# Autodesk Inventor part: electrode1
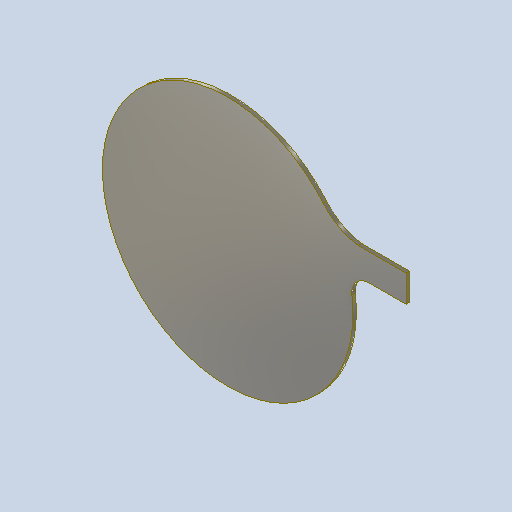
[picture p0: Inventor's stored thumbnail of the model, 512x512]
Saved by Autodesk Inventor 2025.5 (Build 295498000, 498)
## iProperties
Created: 2018-09
Part Number: electrode1
Material: Silver
Document SubType Name: Modeling
Designer: Ev
Density: 10.49 g/cm^3
Appearance: Silver
Author: Ev
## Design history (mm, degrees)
derived "fsr_DF9-40.ipt"
sketch "Boceto1"
  geometry: L1 (35.371, 2.203)-(-7.186, 2.203); L2 (-7.186, 2.203)-(-7.186, -8.504); L3 (-7.186, -8.504)-(35.371, -8.504); L4 (35.371, -8.504)-(35.371, 2.203); 1 further point
  constraints: 8 end point, 2 parallel, 1 horizontal, 1 perpendicular
extrude "Extrusión1" cut sketch "Boceto1" distance "d1" = 5; taper "d2" = 0 deg
feature "electrode1::fsr_DF9-40.ipt" dims "d0" = 10
tag "TaggingFeature1"
body "Solid1"
